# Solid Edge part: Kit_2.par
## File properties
Author: ahadarics
Last saved by: ahadarics
Revision: 76
Sűrűség: 0,000 kg/m^3
Pontosság: 0,990
Username: ahadarics
Dokumentum tartalom típus: 0
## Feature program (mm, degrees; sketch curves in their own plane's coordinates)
base feature "unnamed BaseFeature 1"
sketch for "unnamed Hole 1" plane through (0, 0, 0) normal (0, 0, -1) x-axis (0, -1, 0)
  hole centre (28.25, 28.25) bore radius 3.3235
hole "unnamed Hole 1" through
sketch for "unnamed Hole 2" plane through (0, 0, 0) normal (0, 0, -1) x-axis (0, -1, 0)
  hole centre (-28.25, 28.25) bore radius 3.3235
hole "unnamed Hole 2" through
sketch for "unnamed Hole 3" plane through (0, 0, 0) normal (0, 0, -1) x-axis (0, -1, 0)
  hole centre (-28.25, -28.25) bore radius 3.3235
hole "unnamed Hole 3" through
sketch for "unnamed Hole 4" plane through (0, 0, 0) normal (0, 0, -1) x-axis (0, -1, 0)
  hole centre (28.25, -28.25) bore radius 3.3235
hole "unnamed Hole 4" through
pattern "unnamed Pattern 1" of "unnamed Hole 1", "unnamed Hole 2", "unnamed Hole 3", "unnamed Hole 4"
thread "unnamed Thread 1"
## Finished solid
Body 1: solid body, 293 faces, 734 edges, 457 vertices.
  Faces by surface: plane 140, cylinder 72, swept 61, cone 11, torus 8, spline 1
  Edges by curve: line 431, circle 138, spline 126, ellipse 30, curve on surface 9
Bounding box of the edges (mm; curved faces can reach further): 77.000 x 77.000 x 13.750, from (-38.5, -38.5, 0) to (38.5, 38.5, 13.75).
Cylindrical faces by radius (mm): R0.2 x48, R0.2008 x2, R0.2009 x2, R0.402 x1, R0.4899 x1, R3.3235 x4, R4.283 x1, R4.9 x4, R5.15 x4, R5.25 x4, R6 x1
Conical faces (half-angle, radius in mm at the cone's reference point): 0.5 deg R12 x4, 0.5 deg R13.5 x2, 45 deg R3.6735 x4, 45 deg R6.25 x1
Toroidal faces (ring radius, tube radius in mm): R4.7 r0.2 x8
Planar faces by outward normal: +x 12, +y 14, +z 1, -x 15, -y 13, -z 18, oblique 67
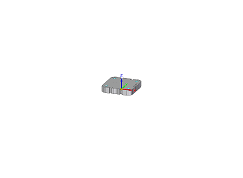
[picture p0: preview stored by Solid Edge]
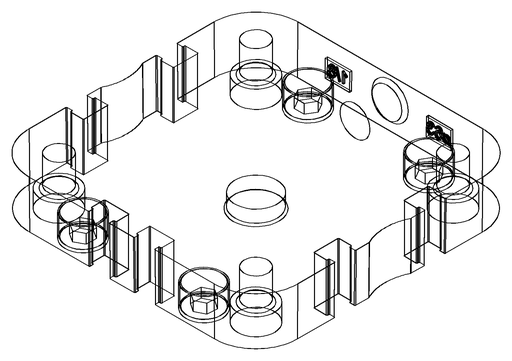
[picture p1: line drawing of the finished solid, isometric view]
